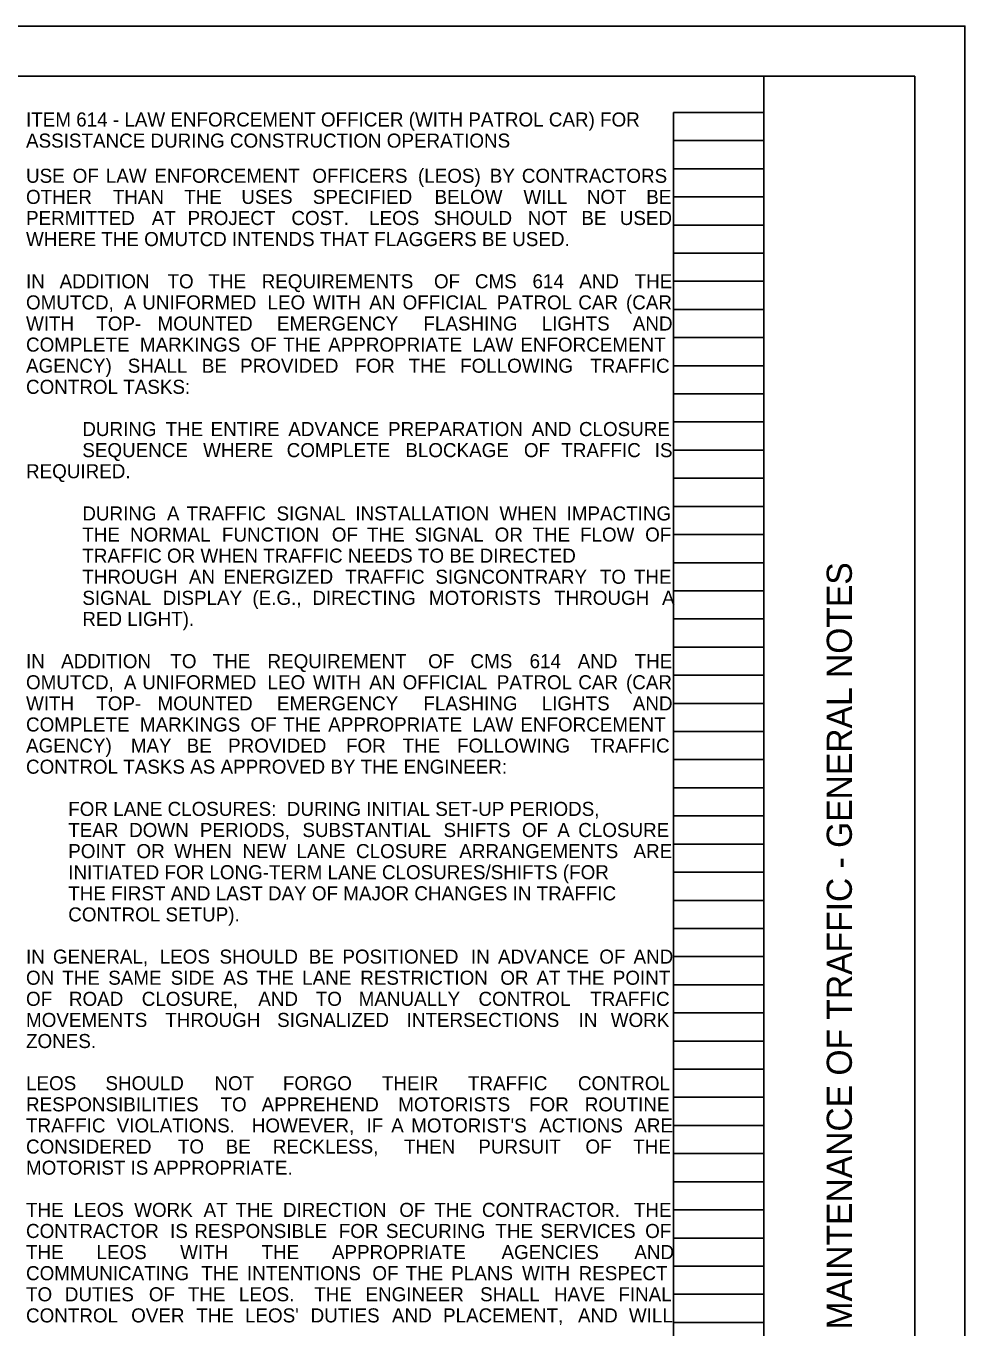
# Model space of a CAD drawing. Extents: x 0 to 34, y 0 to 22.
# Drawn here: x 24.66 to 34, y 9.04 to 22 of the extents above; entities that cross this region are included whole.
import ezdxf

# ---------------------------------------------------------------- set-up
doc = ezdxf.new("R2010")
doc.units = 0
for name, color, linetype in [('SH_Border', 7, 'Continuous'), ('SH_Cut_Line', 7, 'Continuous'), ('SH_Data', 7, 'Continuous'), ('SH_Text', 7, 'Continuous')]:
    doc.layers.add(name, color=color, linetype=linetype)

msp = doc.modelspace()

# ---------------------------------------------------------------- linework, layer by layer
at = {"layer": 'SH_Border'}
msp.add_line((32, 0.5), (32, 21.5), dxfattribs=at)
msp.add_lwpolyline([(1.5, 21.5), (33.5, 21.5), (33.5, 0.5), (1.5, 0.5)], close=True, dxfattribs=at)
at = {"layer": 'SH_Cut_Line'}
msp.add_lwpolyline([(0, 0), (34, 0), (34, 22), (0, 22)], close=True, dxfattribs=at)
at = {"layer": 'SH_Data'}
for p, q in [((31.1, 0.98), (31.1, 21.14)), ((31.1, 21.14), (32, 21.14)), ((32, 0.98), (32, 21.14)), ((31.1, 20.86), (32, 20.86)), ((31.1, 20.58), (32, 20.58)), ((31.1, 20.3), (32, 20.3)), ((31.1, 20.02), (32, 20.02)), ((31.1, 19.74), (32, 19.74)), ((31.1, 19.46), (32, 19.46)), ((31.1, 19.18), (32, 19.18)), ((31.1, 18.9), (32, 18.9)), ((31.1, 18.62), (32, 18.62)), ((31.1, 18.34), (32, 18.34)), ((31.1, 18.06), (32, 18.06)), ((31.1, 17.78), (32, 17.78)), ((31.1, 17.5), (32, 17.5)), ((31.1, 17.22), (32, 17.22)), ((31.1, 16.94), (32, 16.94)), ((31.1, 16.66), (32, 16.66)), ((31.1, 16.38), (32, 16.38)), ((31.1, 16.1), (32, 16.1)), ((31.1, 15.82), (32, 15.82)), ((31.1, 15.54), (32, 15.54)), ((31.1, 15.26), (32, 15.26)), ((31.1, 14.98), (32, 14.98)), ((31.1, 14.7), (32, 14.7)), ((31.1, 14.42), (32, 14.42)), ((31.1, 14.14), (32, 14.14)), ((31.1, 13.86), (32, 13.86)), ((31.1, 13.58), (32, 13.58)), ((31.1, 13.3), (32, 13.3)), ((31.1, 13.02), (32, 13.02)), ((31.1, 12.74), (32, 12.74)), ((31.1, 12.46), (32, 12.46)), ((31.1, 12.18), (32, 12.18)), ((31.1, 11.9), (32, 11.9)), ((31.1, 11.62), (32, 11.62)), ((31.1, 11.34), (32, 11.34)), ((31.1, 11.06), (32, 11.06)), ((31.1, 10.78), (32, 10.78)), ((31.1, 10.5), (32, 10.5)), ((31.1, 10.22), (32, 10.22)), ((31.1, 9.94), (32, 9.94)), ((31.1, 9.66), (32, 9.66)), ((31.1, 9.38), (32, 9.38)), ((31.1, 9.1), (32, 9.1))]:
    msp.add_line(p, q, dxfattribs=at)

# ---------------------------------------------------------------- texts
msp.add_text('MAINTENANCE OF TRAFFIC - GENERAL NOTES', height=0.25, rotation=90, dxfattribs=at).set_placement((32.875, 9.03))
at = {"layer": 'SH_Text'}
for s, p in [('ITEM 614 - LAW ENFORCEMENT OFFICER (WITH PATROL CAR) FOR ', (24.66, 21)), ('ASSISTANCE DURING CONSTRUCTION OPERATIONS', (24.66, 20.79)), ('USE ', (24.66, 20.44)), ('OF ', (25.124, 20.44)), ('LAW ', (25.454, 20.44)), ('ENFORCEMENT ', (25.936, 20.44)), ('OFFICERS ', (27.508, 20.44)), ('(LEOS) ', (28.559, 20.44)), ('BY ', (29.273, 20.44)), ('CONTRACTORS ', (29.592, 20.44)), ('OTHER ', (24.66, 20.23)), ('THAN ', (25.523, 20.23)), ('THE ', (26.233, 20.23)), ('USES ', (26.802, 20.23)), ('SPECIFIED ', (27.513, 20.23)), ('BELOW ', (28.724, 20.23)), ('WILL ', (29.608, 20.23)), ('NOT ', (30.239, 20.23)), ('BE ', (30.83, 20.23)), ('PERMITTED ', (24.66, 20.02)), ('AT ', (25.911, 20.02)), ('PROJECT ', (26.267, 20.02)), ('COST.  ', (27.3, 20.02)), ('LEOS ', (28.073, 20.02)), ('SHOULD ', (28.715, 20.02)), ('NOT ', (29.651, 20.02)), ('BE ', (30.184, 20.02)), ('USED ', (30.566, 20.02)), ('WHERE THE OMUTCD INTENDS THAT FLAGGERS BE USED.', (24.66, 19.81)), ('IN ', (24.66, 19.39)), ('ADDITION ', (24.994, 19.39)), ('TO ', (26.067, 19.39)), ('THE ', (26.474, 19.39)), ('REQUIREMENTS ', (27.004, 19.39)), ('OF ', (28.718, 19.39)), ('CMS ', (29.125, 19.39)), ('614 ', (29.698, 19.39)), ('AND ', (30.163, 19.39)), ('THE ', (30.714, 19.39)), ('OMUTCD, ', (24.66, 19.18)), ('A ', (25.633, 19.18)), ('UNIFORMED ', (25.817, 19.18)), ('LEO ', (27.062, 19.18)), ('WITH ', (27.514, 19.18)), ('AN ', (28.074, 19.18)), ('OFFICIAL ', (28.406, 19.18)), ('PATROL ', (29.343, 19.18)), ('CAR ', (30.154, 19.18)), ('(CAR ', (30.628, 19.18)), ('WITH ', (24.66, 18.97)), ('TOP-', (25.359, 18.97)), ('MOUNTED ', (25.968, 18.97)), ('EMERGENCY ', (27.156, 18.97)), ('FLASHING ', (28.613, 18.97)), ('LIGHTS ', (29.79, 18.97)), ('AND ', (30.696, 18.97)), ('COMPLETE ', (24.66, 18.76)), ('MARKINGS ', (25.793, 18.76)), ('OF ', (26.893, 18.76)), ('THE ', (27.218, 18.76)), ('APPROPRIATE ', (27.666, 18.76)), ('LAW ', (29.1, 18.76)), ('ENFORCEMENT ', (29.577, 18.76)), ('AGENCY) ', (24.66, 18.55)), ('SHALL ', (25.672, 18.55)), ('BE ', (26.409, 18.55)), ('PROVIDED ', (26.79, 18.55)), ('FOR ', (27.933, 18.55)), ('THE ', (28.466, 18.55)), ('FOLLOWING ', (28.978, 18.55)), ('TRAFFIC ', (30.272, 18.55)), ('CONTROL TASKS:', (24.66, 18.34)), ('DURING ', (25.22, 17.92)), ('THE ', (26.048, 17.92)), ('ENTIRE ', (26.496, 17.92)), ('ADVANCE ', (27.269, 17.92)), ('PREPARATION ', (28.261, 17.92)), ('AND ', (29.69, 17.92)), ('CLOSURE ', (30.16, 17.92)), ('SEQUENCE ', (25.22, 17.71)), ('WHERE ', (26.422, 17.71)), ('COMPLETE ', (27.253, 17.71)), ('BLOCKAGE ', (28.433, 17.71)), ('OF ', (29.613, 17.71)), ('TRAFFIC ', (29.985, 17.71)), ('IS ', (30.914, 17.71)), ('REQUIRED.', (24.66, 17.5)), ('DURING ', (25.22, 17.08)), ('A ', (26.062, 17.08)), ('TRAFFIC ', (26.256, 17.08)), ('SIGNAL ', (27.152, 17.08)), ('INSTALLATION ', (27.936, 17.08)), ('WHEN ', (29.369, 17.08)), ('IMPACTING ', (30.037, 17.08)), ('THE ', (25.22, 16.87)), ('NORMAL ', (25.694, 16.87)), ('FUNCTION ', (26.609, 16.87)), ('OF ', (27.702, 16.87)), ('THE ', (28.052, 16.87)), ('SIGNAL ', (28.526, 16.87)), ('OR ', (29.322, 16.87)), ('THE ', (29.698, 16.87)), ('FLOW ', (30.171, 16.87)), ('OF ', (30.819, 16.87)), ('TRAFFIC OR WHEN TRAFFIC NEEDS TO BE DIRECTED ', (25.22, 16.66)), ('THROUGH ', (25.22, 16.45)), ('AN ', (26.28, 16.45)), ('ENERGIZED ', (26.623, 16.45)), ('TRAFFIC ', (27.835, 16.45)), ('SIGNCONTRARY ', (28.732, 16.45)), ('TO ', (30.368, 16.45)), ('THE ', (30.707, 16.45)), ('SIGNAL ', (25.22, 16.24)), ('DISPLAY ', (26.019, 16.24)), ('(E.G., ', (26.912, 16.24)), ('DIRECTING ', (27.508, 16.24)), ('MOTORISTS ', (28.668, 16.24)), ('THROUGH ', (29.913, 16.24)), ('A ', (30.987, 16.24)), ('RED LIGHT).', (25.22, 16.03)), ('IN ', (24.66, 15.61)), ('ADDITION ', (25.009, 15.61)), ('TO ', (26.096, 15.61)), ('THE ', (26.517, 15.61)), ('REQUIREMENT ', (27.062, 15.61)), ('OF ', (28.66, 15.61)), ('CMS ', (29.081, 15.61)), ('614 ', (29.669, 15.61)), ('AND ', (30.148, 15.61)), ('THE ', (30.714, 15.61)), ('(CAR ', (30.628, 15.4)), ('OMUTCD, ', (24.66, 15.4)), ('A ', (25.633, 15.4)), ('UNIFORMED ', (25.817, 15.4)), ('LEO ', (27.062, 15.4)), ('WITH ', (27.514, 15.4)), ('AN ', (28.074, 15.4)), ('OFFICIAL ', (28.406, 15.4)), ('PATROL ', (29.343, 15.4)), ('CAR ', (30.154, 15.4)), ('WITH ', (24.66, 15.19)), ('TOP-', (25.359, 15.19)), ('MOUNTED ', (25.968, 15.19)), ('EMERGENCY ', (27.156, 15.19)), ('FLASHING ', (28.613, 15.19)), ('LIGHTS ', (29.79, 15.19)), ('AND ', (30.696, 15.19)), ('COMPLETE ', (24.66, 14.98)), ('MARKINGS ', (25.793, 14.98)), ('OF ', (26.893, 14.98)), ('THE ', (27.218, 14.98)), ('APPROPRIATE ', (27.666, 14.98)), ('LAW ', (29.1, 14.98)), ('ENFORCEMENT ', (29.577, 14.98)), ('AGENCY) ', (24.66, 14.77)), ('MAY ', (25.702, 14.77)), ('BE ', (26.258, 14.77)), ('PROVIDED ', (26.67, 14.77)), ('FOR ', (27.843, 14.77)), ('THE ', (28.406, 14.77)), ('FOLLOWING ', (28.948, 14.77)), ('TRAFFIC ', (30.272, 14.77)), ('CONTROL TASKS AS APPROVED BY THE ENGINEER:', (24.66, 14.56)), ('FOR LANE CLOSURES:  DURING INITIAL SET-UP PERIODS, ', (25.08, 14.14)), ('TEAR ', (25.08, 13.93)), ('DOWN ', (25.686, 13.93)), ('PERIODS, ', (26.39, 13.93)), ('SUBSTANTIAL ', (27.409, 13.93)), ('SHIFTS ', (28.813, 13.93)), ('OF ', (29.593, 13.93)), ('A ', (29.945, 13.93)), ('CLOSURE ', (30.153, 13.93)), ('POINT ', (25.08, 13.72)), ('OR ', (25.759, 13.72)), ('CLOSURE ', (27.943, 13.72)), ('ARRANGEMENTS ', (28.97, 13.72)), ('WHEN ', (26.134, 13.72)), ('NEW ', (26.813, 13.72)), ('LANE ', (27.35, 13.72)), ('ARE ', (30.703, 13.72)), ('INITIATED FOR LONG-TERM LANE CLOSURES/SHIFTS (FOR ', (25.08, 13.51)), ('THE FIRST AND LAST DAY OF MAJOR CHANGES IN TRAFFIC ', (25.08, 13.3)), ('CONTROL SETUP).', (25.08, 13.09)), ('IN ', (24.66, 12.67)), ('GENERAL, ', (24.928, 12.67)), ('LEOS ', (25.99, 12.67)), ('SHOULD ', (26.585, 12.67)), ('BE ', (27.473, 12.67)), ('POSITIONED ', (27.807, 12.67)), ('IN ', (29.086, 12.67)), ('ADVANCE ', (29.355, 12.67)), ('OF ', (30.363, 12.67)), ('AND ', (30.703, 12.67)), ('ON ', (24.66, 12.46)), ('THE ', (25.02, 12.46)), ('SAME ', (25.478, 12.46)), ('SIDE ', (26.099, 12.46)), ('AS ', (26.622, 12.46)), ('THE ', (26.95, 12.46)), ('LANE ', (27.407, 12.46)), ('RESTRICTION ', (27.985, 12.46)), ('OR ', (29.378, 12.46)), ('AT ', (29.738, 12.46)), ('THE ', (30.04, 12.46)), ('POINT ', (30.497, 12.46)), ('OF ', (24.66, 12.25)), ('ROAD ', (25.087, 12.25)), ('CLOSURE, ', (25.811, 12.25)), ('AND ', (26.97, 12.25)), ('TO ', (27.542, 12.25)), ('MANUALLY ', (27.969, 12.25)), ('CONTROL ', (29.161, 12.25)), ('TRAFFIC ', (30.272, 12.25)), ('MOVEMENTS ', (24.66, 12.04)), ('THROUGH ', (26.045, 12.04)), ('SIGNALIZED ', (27.158, 12.04)), ('INTERSECTIONS ', (28.446, 12.04)), ('IN ', (30.157, 12.04)), ('WORK ', (30.477, 12.04)), ('ZONES.', (24.66, 11.83)), ('LEOS ', (24.66, 11.41)), ('SHOULD ', (25.45, 11.41)), ('NOT ', (26.534, 11.41)), ('FORGO ', (27.215, 11.41)), ('THEIR ', (28.2, 11.41)), ('TRAFFIC ', (29.056, 11.41)), ('CONTROL ', (30.15, 11.41)), ('RESPONSIBILITIES ', (24.66, 11.2)), ('TO ', (26.595, 11.2)), ('APPREHEND ', (27.004, 11.2)), ('MOTORISTS ', (28.363, 11.2)), ('FOR ', (29.664, 11.2)), ('ROUTINE ', (30.218, 11.2)), ('TRAFFIC ', (24.66, 10.99)), ('VIOLATIONS.  ', (25.562, 10.99)), ('HOWEVER, ', (26.906, 10.99)), ('IF ', (28.047, 10.99)), ('A ', (28.293, 10.99)), ("MOTORIST'S ", (28.492, 10.99)), ('ACTIONS ', (29.765, 10.99)), ('ARE ', (30.711, 10.99)), ('CONSIDERED ', (24.66, 10.78)), ('TO ', (26.171, 10.78)), ('BE ', (26.646, 10.78)), ('RECKLESS, ', (27.114, 10.78)), ('THEN ', (28.42, 10.78)), ('PURSUIT ', (29.159, 10.78)), ('OF ', (30.225, 10.78)), ('THE ', (30.7, 10.78)), ('MOTORIST IS APPROPRIATE.', (24.66, 10.57)), ('THE ', (24.66, 10.15)), ('LEOS ', (25.133, 10.15)), ('WORK ', (25.736, 10.15)), ('AT ', (26.426, 10.15)), ('THE ', (26.743, 10.15)), ('DIRECTION ', (27.215, 10.15)), ('OF ', (28.373, 10.15)), ('THE ', (28.722, 10.15)), ('CONTRACTOR. ', (29.195, 10.15)), ('THE ', (30.707, 10.15)), ('CONTRACTOR ', (24.66, 9.94)), ('IS ', (26.093, 9.94)), ('RESPONSIBLE ', (26.334, 9.94)), ('FOR ', (27.771, 9.94)), ('SECURING ', (28.24, 9.94)), ('THE ', (29.329, 9.94)), ('SERVICES ', (29.777, 9.94)), ('OF ', (30.819, 9.94)), ('THE ', (24.66, 9.73)), ('LEOS ', (25.361, 9.73)), ('WITH ', (26.193, 9.73)), ('THE ', (27.002, 9.73)), ('APPROPRIATE ', (27.703, 9.73)), ('AGENCIES ', (29.39, 9.73)), ('AND ', (30.711, 9.73)), ('COMMUNICATING ', (24.66, 9.52)), ('THE ', (26.403, 9.52)), ('INTENTIONS ', (26.858, 9.52)), ('OF ', (28.105, 9.52)), ('THE ', (28.436, 9.52)), ('PLANS ', (28.89, 9.52)), ('WITH ', (29.594, 9.52)), ('RESPECT ', (30.157, 9.52)), ('TO ', (24.66, 9.31)), ('DUTIES ', (25.046, 9.31)), ('OF ', (25.882, 9.31)), ('THE ', (26.269, 9.31)), ('LEOS.  ', (26.778, 9.31)), ('THE ', (27.527, 9.31)), ('ENGINEER ', (28.037, 9.31)), ('SHALL ', (29.177, 9.31)), ('HAVE ', (29.912, 9.31)), ('FINAL ', (30.552, 9.31)), ('CONTROL ', (24.66, 9.1)), ('OVER ', (25.706, 9.1)), ('THE ', (26.354, 9.1)), ("LEOS' ", (26.838, 9.1)), ('DUTIES ', (27.491, 9.1)), ('AND ', (28.301, 9.1)), ('PLACEMENT, ', (28.808, 9.1)), ('AND ', (30.151, 9.1)), ('WILL ', (30.657, 9.1))]:
    msp.add_text(s, height=0.14, dxfattribs=at).set_placement(p)

doc.saveas('drawing.dxf')
